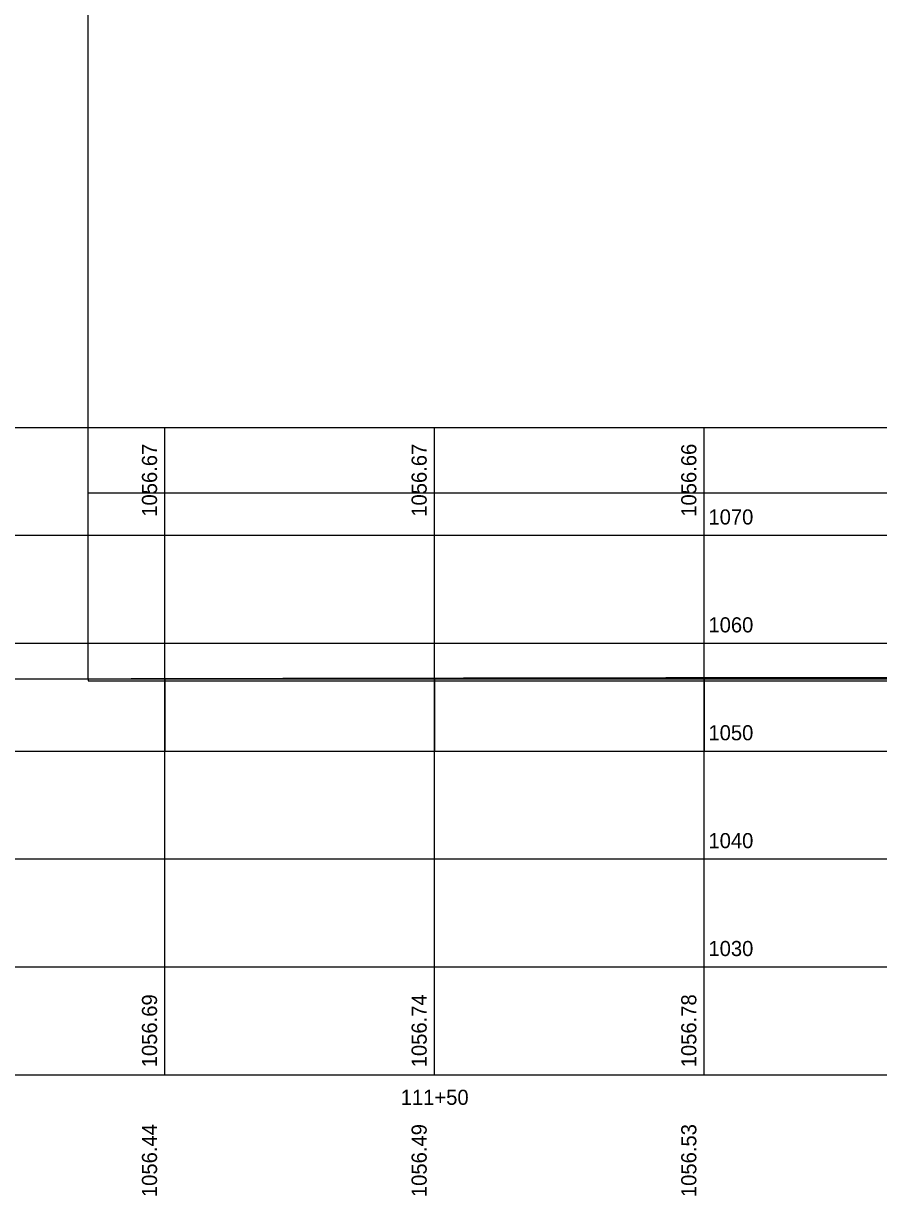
# Model space of a CAD drawing. Extents: x -2063 to 2068, y 79 to 1202.
# Drawn here: x -1757.4 to -1678.2, y 250.8 to 359.4 of the extents above; entities that cross this region are included whole.
import ezdxf

# ---------------------------------------------------------------- set-up
doc = ezdxf.new("R2010")
doc.units = 0
for name, color, linetype in [('PF_X_Ground_Line', 7, 'Continuous'), ('SC_Scratch1', 7, 'Continuous'), ('SC_Scratch2', 7, 'Continuous'), ('SC_Scratch3', 7, 'Continuous'), ('XS_P_Pavt_Surface', 7, 'Continuous')]:
    doc.layers.add(name, color=color, linetype=linetype)

msp = doc.modelspace()

# ---------------------------------------------------------------- linework, layer by layer
at = {"layer": 'PF_X_Ground_Line'}
for centre, radius, start, end in [((-1606.83, -62201.38), 62500.19, 90.0638229, 90.1031323), ((-1606.83, -62201.65), 62500.46, 90.1031323, 90.1489687)]:
    msp.add_arc(centre, radius, start, end, dxfattribs=at)
at = {"layer": 'SC_Scratch1'}
for p, q in [((-1969.33, 321.97), (-1244.33, 321.97)), ((-1744.33, 261.97), (-1744.33, 321.97)), ((-1719.33, 261.97), (-1719.33, 321.97)), ((-1694.33, 261.97), (-1694.33, 321.97)), ((-1969.33, 311.97), (-1244.33, 311.97)), ((-1969.33, 301.97), (-1244.33, 301.97)), ((-1969.33, 291.97), (-1244.33, 291.97)), ((-1969.33, 281.97), (-1244.33, 281.97)), ((-1969.33, 271.97), (-1244.33, 271.97)), ((-1969.33, 261.97), (-1244.33, 261.97))]:
    msp.add_line(p, q, dxfattribs=at)
at = {"layer": 'SC_Scratch2'}
for p, q in [((-1744.33, 298.64), (-1744.33, 291.97)), ((-1719.33, 298.63), (-1719.33, 291.97)), ((-1694.33, 298.63), (-1694.33, 291.97))]:
    msp.add_line(p, q, dxfattribs=at)
at = {"layer": 'SC_Scratch3'}
for p, q in [((-1751.45, 298.64), (-1751.45, 1078.48)), ((-1751.45, 315.92), (-1651.45, 315.92)), ((-1744.33, 291.97), (-1744.33, 298.66)), ((-1719.33, 291.97), (-1719.33, 298.71)), ((-1694.33, 291.97), (-1694.33, 298.75))]:
    msp.add_line(p, q, dxfattribs=at)
at = {"layer": 'XS_P_Pavt_Surface'}
for p, q in [((-1651.45, 298.62), (-1751.45, 298.64)), ((-1751.45, 298.64), (-1751.45, 298.49)), ((-1751.45, 298.49), (-1676.45, 298.48))]:
    msp.add_line(p, q, dxfattribs=at)

# ---------------------------------------------------------------- texts
at = {"layer": 'SC_Scratch1'}
for s, p in [('1056.67', (-1745.06, 313.69)), ('1056.67', (-1720.06, 313.69)), ('1056.66', (-1695.06, 313.69)), ('1056.69', (-1745.06, 262.66)), ('1056.74', (-1720.06, 262.66)), ('1056.78', (-1695.06, 262.66)), ('1056.44', (-1745.06, 250.63)), ('1056.49', (-1720.06, 250.63)), ('1056.53', (-1695.06, 250.63))]:
    msp.add_text(s, height=1.4, rotation=90, dxfattribs=at).set_placement(p)
for s, p in [('1070', (-1693.94, 312.97)), ('1060', (-1693.94, 302.97)), ('1050', (-1693.94, 292.97)), ('1040', (-1693.94, 282.97)), ('1030', (-1693.94, 272.97)), ('111+50', (-1722.47, 259.18))]:
    msp.add_text(s, height=1.4, dxfattribs=at).set_placement(p)

doc.saveas('drawing.dxf')
